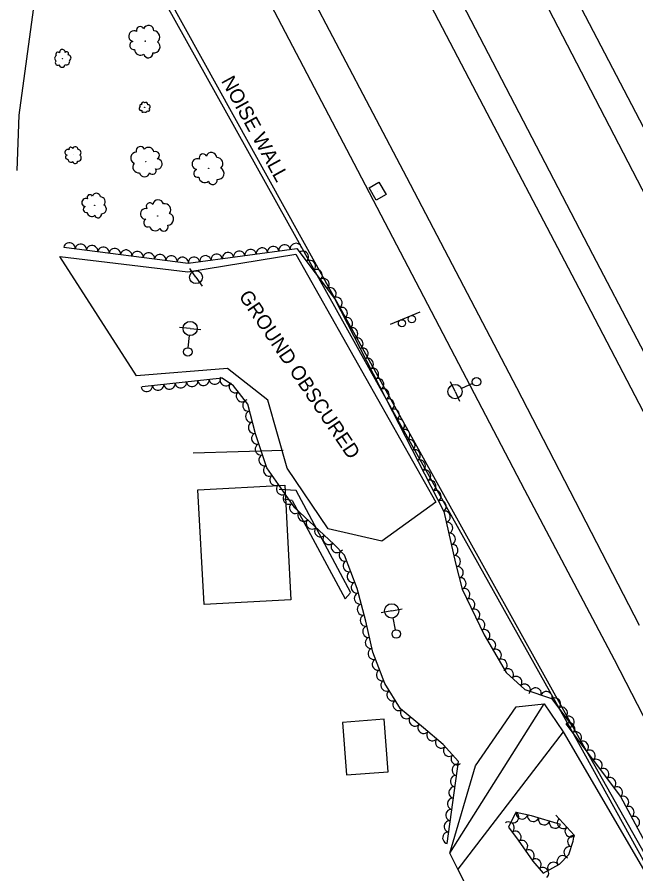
# Model space of a CAD drawing. Extents: x 1722896 to 1754269, y 648279 to 666297.
# Drawn here: x 1727428.2 to 1727645, y 654279.2 to 654579.3 of the extents above; entities that cross this region are included whole.
import ezdxf

# ---------------------------------------------------------------- set-up
doc = ezdxf.new("R2010")
doc.units = 0
for name, color, linetype in [('DESIGN - CENTERLINE - Proposed Text', 7, 'Continuous'), ('DESIGN - PUBLIC HEARING - Shapes', 7, 'Continuous'), ('DESIGN - SCRATCH - User 1', 7, 'Continuous'), ('SURVEY - CENTERLINE - Preliminary', 7, 'Continuous'), ('SURVEY - CENTERLINE - Preliminary Text', 7, 'Continuous'), ('SURVEY - DRAINAGE - Natural Features', 7, 'Continuous'), ('SURVEY - DTM - Breaklines', 7, 'Continuous'), ('SURVEY - VEGETATION - Features with Text', 7, 'Continuous')]:
    doc.layers.add(name, color=color, linetype=linetype)

msp = doc.modelspace()

# ---------------------------------------------------------------- linework, layer by layer
at = {"layer": 'DESIGN - CENTERLINE - Proposed Text'}
for points in [[(1727521.94, 654415.39), (1727524.08, 654375.16), (1727493.7, 654373.54), (1727491.56, 654413.77)], [(1727558.24, 654315), (1727556.82, 654333.41), (1727542.2, 654332.28), (1727543.62, 654313.88)]]:
    msp.add_lwpolyline(points, close=True, dxfattribs=at)
for points in [[(1727526, 654413.45), (1727519.97, 654413.84)], [(1727545.15, 654377.67), (1727526, 654413.45)], [(1727524.53, 654409.96), (1727521.55, 654410.51)], [(1727524.53, 654409.96), (1727543.11, 654375.61), (1727544.9, 654377.49)]]:
    msp.add_lwpolyline(points, dxfattribs=at)
at = {"layer": 'DESIGN - PUBLIC HEARING - Shapes'}
msp.add_line((1727559.02, 654471.72), (1727569.36, 654476.04), dxfattribs=at)
for centre in [(1727563.02, 654472.07), (1727566.48, 654473.51)]:
    msp.add_circle(centre, 1.25, dxfattribs=at)
at = {"layer": 'DESIGN - SCRATCH - User 1'}
for points in [[(1727621.97, 654330.39), (1727565.01, 654432.18), (1727473.36, 654596.48), (1727444.29, 654648.43), (1727445.92, 654649.54), (1727574.11, 654418.37), (1727622.54, 654331.36), (1727621.97, 654330.39)], [(1727622.54, 654331.36), (1727686.73, 654217.77), (1727717.7, 654165.84), (1727754.59, 654120.21), (1727781.55, 654068.35), (1727801.08, 654028.51), (1727824.69, 653960.51), (1727834.36, 653937.28), (1727857, 653885.22), (1727876.48, 653842.06), (1727927.37, 653734.57), (1727927.59, 653734.45)], [(1727927.59, 653734.45), (1727926.17, 653733.65), (1727871.54, 653849.39), (1727850.91, 653896.35), (1727825.81, 653953.49), (1727800.77, 654025.96), (1727785.37, 654057.35), (1727753.48, 654119.66), (1727717.18, 654164.37), (1727672.06, 654239.76), (1727621.97, 654330.39)]]:
    msp.add_lwpolyline(points, dxfattribs=at)
at = {"layer": 'SURVEY - CENTERLINE - Preliminary'}
for points in [[(1727443.16, 654495.41), (1727488, 654490.06), (1727525.83, 654496.28), (1727574.91, 654409.36), (1727555.92, 654395.79), (1727537.15, 654400.12), (1727522.77, 654421.34), (1727516.06, 654445.1), (1727501.95, 654456.21), (1727470.05, 654453.63), (1727443.16, 654495.41)], [(1727579.83, 654286.49), (1727588.84, 654317.11), (1727602.99, 654337.68), (1727612.89, 654338.81), (1727619.49, 654329.03), (1727582.65, 654280.92), (1727579.83, 654286.49)], [(1727612.89, 654338.81), (1727619.49, 654329.03), (1727662.34, 654255.54), (1727674.34, 654234.16), (1727664.05, 654232.84), (1727648.66, 654245.66), (1727604.39, 654235.79), (1727598.61, 654249.64), (1727582.65, 654280.92), (1727579.83, 654286.49), (1727612.89, 654338.81)]]:
    msp.add_lwpolyline(points, dxfattribs=at)
at = {"layer": 'SURVEY - CENTERLINE - Preliminary Text'}
for points in [[(1727480.36, 654860.59), (1727517.38, 654790.02), (1727553.54, 654721.23), (1727589.42, 654652.68), (1727621.82, 654590.18), (1727658.34, 654520.12), (1727699.55, 654441.02)], [(1727477.66, 654844.03), (1727487.15, 654825.93), (1727548.9, 654707.43), (1727604.51, 654601.23), (1727660.16, 654493.92), (1727693.17, 654431.8)], [(1727676.45, 654407.23), (1727629.94, 654496.13), (1727562.95, 654624.9), (1727499.94, 654745.76), (1727460.45, 654821.38)], [(1727670.06, 654398.14), (1727625.13, 654484.21), (1727587.89, 654555.22), (1727538.84, 654649.08), (1727490.42, 654741.64), (1727470.74, 654779.75)], [(1727462.93, 654717.36), (1727491.7, 654662.04), (1727529.25, 654590.6), (1727564.63, 654523.18), (1727603.1, 654449.52), (1727646.13, 654366.33)], [(1727459.16, 654693.93), (1727498.07, 654619.99), (1727547.4, 654525.69), (1727605.96, 654413.77), (1727637.32, 654354.34)], [(1727428.2, 654525.58), (1727428.87, 654544.95), (1727434.27, 654584.37), (1727440.35, 654629.65)], [(1727489.9, 654426.69), (1727521.41, 654427.67)], [(1727637.32, 654354.34), (1727659.52, 654311.28), (1727683.82, 654265.75), (1727710.26, 654216.86)]]:
    msp.add_lwpolyline(points, dxfattribs=at)
at = {"layer": 'SURVEY - DRAINAGE - Natural Features'}
msp.add_line((1727554.49, 654518.31), (1727554.49, 654518.31), dxfattribs=at)
msp.add_lwpolyline([(1727551.5, 654519.46), (1727554.96, 654521.48), (1727557.48, 654517.17), (1727554.03, 654515.14), (1727551.5, 654519.46)], dxfattribs=at)
at = {"layer": 'SURVEY - DTM - Breaklines'}
for p, q in [((1727490.86, 654488.21), (1727488.73, 654491.29)), ((1727490.86, 654488.21), (1727492.99, 654485.12)), ((1727488.82, 654470.23), (1727485.09, 654470.6)), ((1727488.82, 654470.23), (1727492.55, 654469.86)), ((1727488.15, 654463.51), (1727488.57, 654467.74)), ((1727581.63, 654448.15), (1727580.06, 654451.55)), ((1727587.76, 654450.97), (1727583.9, 654449.19)), ((1727581.63, 654448.15), (1727583.2, 654444.74)), ((1727559.42, 654371.34), (1727555.74, 654370.6)), ((1727559.42, 654371.34), (1727563.09, 654372.08)), ((1727560.74, 654364.72), (1727559.91, 654368.89))]:
    msp.add_line(p, q, dxfattribs=at)
for centre, radius in [((1727490.86, 654488.21), 2.25), ((1727488.82, 654470.23), 2.5), ((1727488, 654462.02), 1.5), ((1727589.12, 654451.6), 1.5), ((1727581.63, 654448.15), 2.5), ((1727559.42, 654371.34), 2.5), ((1727561.04, 654363.25), 1.5)]:
    msp.add_circle(centre, radius, dxfattribs=at)
at = {"layer": 'SURVEY - VEGETATION - Features with Text'}
for points in [[(1727444.56, 654498.67), (1727488.14, 654493.07), (1727526.25, 654498.26), (1727539.39, 654480.79), (1727577.64, 654406.11), (1727581.78, 654388.07), (1727584.1, 654378.91), (1727591.86, 654362.96), (1727599.52, 654349.78), (1727606.08, 654343.75), (1727615.4, 654340.62), (1727623.56, 654329.77)], [(1727578.88, 654289.91), (1727582.85, 654318.64), (1727577.44, 654324.54), (1727570.52, 654330.37), (1727562.55, 654337.09), (1727557.08, 654345.94), (1727552.82, 654356.93), (1727550.32, 654367.79), (1727547.3, 654379.17), (1727542.85, 654390.83), (1727539.15, 654394.72), (1727525.48, 654407.44), (1727515.71, 654421.44), (1727511.66, 654433.3), (1727508.99, 654443.79), (1727504.04, 654450.16), (1727500.03, 654452.86), (1727472.01, 654449.86)], [(1727620.44, 654331.82), (1727639.55, 654306.32), (1727668, 654253.51), (1727701.3, 654204.59), (1727718.06, 654176.14), (1727729.46, 654166.58), (1727734.69, 654156.89), (1727740.47, 654144.96), (1727749.36, 654127.63), (1727758.01, 654116.35), (1727776.45, 654083.72), (1727777.95, 654074.34), (1727772.29, 654075.58), (1727763.54, 654080.4), (1727757.81, 654069.22), (1727754.36, 654069.14), (1727749.06, 654073.59), (1727741.42, 654080.65), (1727731.8, 654075.75), (1727704.78, 654053.2)], [(1727618.54, 654296.53), (1727608.43, 654299.62), (1727603.08, 654300.72), (1727602.57, 654300.11), (1727600.37, 654295.57), (1727603.69, 654291.1), (1727608.9, 654283.69), (1727612.52, 654279.52), (1727618.26, 654282.64), (1727621.43, 654286.04), (1727622.96, 654290.65), (1727623.3, 654292.74), (1727616.9, 654299.76)]]:
    msp.add_lwpolyline(points, dxfattribs=at)
for centre, radius in [((1727473.07, 654570.87), 0.0661), ((1727444.13, 654564.75), 0.0346), ((1727472.89, 654547.69), 0.022), ((1727447.96, 654531.04), 0.0346), ((1727473.26, 654528.71), 0.0629), ((1727495.35, 654526.36), 0.0658), ((1727455.35, 654513.34), 0.0503), ((1727477.43, 654509.68), 0.0656)]:
    msp.add_circle(centre, radius, dxfattribs=at)
for centre, radius, start, end in [((1727469.19, 654572.6), 1.89, 62.0023, 255.422), ((1727471.29, 654574.73), 1.3, 21.9816, 200.7272), ((1727474.24, 654574.47), 1.89, 359.8654, 156.6543), ((1727476, 654572.31), 2.16, 308.9182, 86.4424), ((1727469.08, 654569.38), 1.44, 104.6209, 281.9401), ((1727476.14, 654568.86), 2.14, 259.814, 55.6525), ((1727442.39, 654564.86), 1.07, 116.2169, 243.0626), ((1727442.51, 654566.28), 0.753, 40.9299, 218.249), ((1727444.05, 654566.98), 0.99, 358.3112, 191.7309), ((1727445.53, 654566.48), 0.681, 318.2905, 137.0361), ((1727446.09, 654565.04), 0.992, 296.1743, 92.9633), ((1727471.41, 654567.97), 2.04, 179.908, 306.7537), ((1727474.19, 654566.61), 1.58, 190.0669, 5.0672), ((1727442.4, 654563.24), 0.828, 126.3758, 301.3761), ((1727443.91, 654562.84), 1.12, 196.1229, 351.9614), ((1727445.49, 654563.71), 1.13, 245.2271, 22.7513), ((1727471.55, 654547.23), 0.629, 104.9373, 298.357), ((1727471.58, 654548.23), 0.433, 64.9166, 243.6623), ((1727472.36, 654548.83), 0.631, 42.8005, 199.5894), ((1727473.28, 654548.71), 0.719, 351.8532, 129.3774), ((1727474.13, 654546.91), 0.527, 233.0019, 48.0022), ((1727474.1, 654547.9), 0.714, 302.749, 98.5875), ((1727472.26, 654546.42), 0.479, 147.556, 324.8751), ((1727473.15, 654546.61), 0.679, 222.843, 349.6887), ((1727445.93, 654531.95), 0.989, 61.9058, 255.3255), ((1727447.03, 654533.06), 0.68, 21.8851, 200.6308), ((1727448.57, 654532.92), 0.991, 359.769, 156.5579), ((1727449.49, 654531.8), 1.13, 308.8217, 86.3459), ((1727471.4, 654532.46), 1.51, 21.6537, 196.654), ((1727474.25, 654531.73), 1.94, 11.4948, 138.3405), ((1727476.7, 654530.86), 1.37, 296.2078, 113.5269), ((1727445.86, 654530.27), 0.753, 104.5245, 281.8436), ((1727447.09, 654529.53), 1.07, 179.8115, 306.6572), ((1727449.56, 654529.99), 1.12, 259.7175, 55.556), ((1727470.01, 654529.99), 2.04, 91.4008, 247.2393), ((1727477.21, 654527.84), 1.8, 253.5891, 87.0088), ((1727491.37, 654527.82), 1.88, 66.0002, 259.4199), ((1727493.31, 654530.08), 1.3, 25.9795, 204.7251), ((1727496.26, 654530.02), 1.89, 3.8633, 160.6523), ((1727498.15, 654528), 2.15, 312.9161, 90.4403), ((1727448.54, 654528.81), 0.827, 189.9704, 4.9707), ((1727470.8, 654526.8), 2.05, 140.505, 278.0292), ((1727498.54, 654524.59), 2.14, 263.8119, 59.6504), ((1727472.86, 654525.13), 1.8, 191.4523, 348.2412), ((1727475.65, 654525.45), 1.24, 213.5684, 32.3141), ((1727491.48, 654524.61), 1.43, 108.6188, 285.938), ((1727493.9, 654523.37), 2.03, 183.9059, 310.7516), ((1727496.75, 654522.21), 1.58, 194.0648, 9.0651), ((1727455.95, 654516.15), 1.44, 5.8636, 162.6525), ((1727452.28, 654514.34), 1.44, 68.0004, 261.4201), ((1727453.7, 654516.12), 0.989, 27.9797, 206.7254), ((1727457.45, 654514.66), 1.64, 314.9163, 92.4405), ((1727477.63, 654513.43), 1.88, 14.6718, 171.4607), ((1727452.45, 654511.9), 1.09, 110.6191, 287.9382), ((1727457.83, 654512.07), 1.63, 265.8121, 61.6506), ((1727473.27, 654510.36), 1.87, 76.8086, 270.2283), ((1727474.74, 654512.94), 1.29, 36.7879, 215.5336), ((1727479.87, 654511.81), 2.14, 323.7245, 101.2487), ((1727454.33, 654511.01), 1.55, 185.9061, 312.7518), ((1727456.53, 654510.21), 1.2, 196.065, 11.0653), ((1727473.97, 654507.24), 1.43, 119.4273, 296.7464), ((1727480.88, 654508.54), 2.13, 274.6203, 70.4588), ((1727476.57, 654506.48), 2.02, 194.7143, 321.56), ((1727479.58, 654505.89), 1.57, 204.8732, 19.8735)]:
    msp.add_arc(centre, radius, start, end, dxfattribs=at)
for centre, major_axis in [((1727446.55, 654498.42), (1.98, -0.26)), ((1727450.52, 654497.91), (1.98, -0.26)), ((1727454.48, 654497.4), (1.98, -0.26)), ((1727521.89, 654497.66), (1.98, 0.27)), ((1727525.86, 654498.2), (1.98, 0.27)), ((1727458.45, 654496.89), (1.98, -0.26)), ((1727462.42, 654496.38), (1.98, -0.26)), ((1727466.39, 654495.87), (1.98, -0.26)), ((1727470.35, 654495.35), (1.98, -0.26)), ((1727474.32, 654494.84), (1.98, -0.26)), ((1727478.29, 654494.33), (1.98, -0.26)), ((1727498.11, 654494.42), (1.98, 0.27)), ((1727502.08, 654494.96), (1.98, 0.27)), ((1727506.04, 654495.5), (1.98, 0.27)), ((1727510, 654496.04), (1.98, 0.27)), ((1727513.97, 654496.58), (1.98, 0.27)), ((1727517.93, 654497.12), (1.98, 0.27)), ((1727528.42, 654495.38), (1.2, -1.6)), ((1727482.25, 654493.82), (1.98, -0.26)), ((1727486.22, 654493.31), (1.98, -0.26)), ((1727490.19, 654493.34), (1.98, 0.27)), ((1727494.15, 654493.88), (1.98, 0.27)), ((1727530.82, 654492.18), (1.2, -1.6)), ((1727533.22, 654488.98), (1.2, -1.6)), ((1727535.63, 654485.79), (1.2, -1.6)), ((1727538.03, 654482.59), (1.2, -1.6)), ((1727540.18, 654479.24), (0.91, -1.78)), ((1727542.01, 654475.68), (0.91, -1.78)), ((1727543.83, 654472.12), (0.91, -1.78)), ((1727545.65, 654468.55), (0.91, -1.78)), ((1727547.48, 654464.99), (0.91, -1.78)), ((1727549.3, 654461.43), (0.91, -1.78)), ((1727551.12, 654457.87), (0.91, -1.78)), ((1727552.95, 654454.31), (0.91, -1.78)), ((1727485.56, 654451.31), (-1.99, -0.21)), ((1727489.53, 654451.74), (-1.99, -0.21)), ((1727493.51, 654452.16), (-1.99, -0.21)), ((1727497.49, 654452.59), (-1.99, -0.21)), ((1727501.23, 654452.06), (-1.66, 1.12)), ((1727504.42, 654449.68), (-1.23, 1.58)), ((1727554.77, 654450.75), (0.91, -1.78)), ((1727473.62, 654450.04), (-1.99, -0.21)), ((1727477.6, 654450.46), (-1.99, -0.21)), ((1727481.58, 654450.89), (-1.99, -0.21)), ((1727556.59, 654447.19), (0.91, -1.78)), ((1727506.87, 654446.52), (-1.23, 1.58)), ((1727558.42, 654443.63), (0.91, -1.78)), ((1727509.13, 654443.27), (-0.49, 1.94)), ((1727560.24, 654440.07), (0.91, -1.78)), ((1727510.11, 654439.39), (-0.49, 1.94)), ((1727511.1, 654435.51), (-0.49, 1.94)), ((1727562.06, 654436.51), (0.91, -1.78)), ((1727512.22, 654431.68), (-0.65, 1.89)), ((1727563.89, 654432.95), (0.91, -1.78)), ((1727565.71, 654429.39), (0.91, -1.78)), ((1727513.51, 654427.89), (-0.65, 1.89)), ((1727567.54, 654425.83), (0.91, -1.78)), ((1727514.8, 654424.11), (-0.65, 1.89)), ((1727569.36, 654422.27), (0.91, -1.78)), ((1727516.39, 654420.47), (-1.14, 1.64)), ((1727518.68, 654417.19), (-1.14, 1.64)), ((1727571.18, 654418.71), (0.91, -1.78)), ((1727520.97, 654413.91), (-1.14, 1.64)), ((1727573.01, 654415.15), (0.91, -1.78)), ((1727523.26, 654410.63), (-1.14, 1.64)), ((1727574.83, 654411.59), (0.91, -1.78)), ((1727576.65, 654408.03), (0.91, -1.78)), ((1727525.56, 654407.37), (-1.46, 1.36)), ((1727578.05, 654404.32), (0.45, -1.95)), ((1727528.49, 654404.64), (-1.46, 1.36)), ((1727531.42, 654401.92), (-1.46, 1.36)), ((1727534.35, 654399.19), (-1.46, 1.36)), ((1727578.94, 654400.42), (0.45, -1.95)), ((1727537.28, 654396.47), (-1.46, 1.36)), ((1727579.84, 654396.52), (0.45, -1.95)), ((1727540.14, 654393.68), (-1.38, 1.45)), ((1727580.74, 654392.62), (0.45, -1.95)), ((1727542.87, 654390.76), (-0.71, 1.87)), ((1727544.3, 654387.03), (-0.71, 1.87)), ((1727581.63, 654388.72), (0.45, -1.95)), ((1727582.6, 654384.84), (0.49, -1.94)), ((1727545.73, 654383.29), (-0.71, 1.87)), ((1727583.58, 654380.96), (0.49, -1.94)), ((1727547.15, 654379.55), (-0.71, 1.87)), ((1727584.92, 654377.22), (0.88, -1.8)), ((1727548.22, 654375.7), (-0.51, 1.93)), ((1727549.25, 654371.83), (-0.51, 1.93)), ((1727586.67, 654373.62), (0.88, -1.8)), ((1727588.42, 654370.02), (0.88, -1.8)), ((1727550.27, 654367.97), (-0.51, 1.93)), ((1727590.17, 654366.43), (0.88, -1.8)), ((1727551.18, 654364.07), (-0.45, 1.95)), ((1727591.93, 654362.83), (1.01, -1.73)), ((1727552.07, 654360.17), (-0.45, 1.95)), ((1727593.94, 654359.38), (1.01, -1.73)), ((1727553.06, 654356.3), (-0.72, 1.86)), ((1727595.95, 654355.92), (1.01, -1.73)), ((1727554.51, 654352.57), (-0.72, 1.86)), ((1727597.96, 654352.46), (1.01, -1.73)), ((1727555.96, 654348.84), (-0.72, 1.86)), ((1727600.19, 654349.17), (1.47, -1.35)), ((1727557.55, 654345.19), (-1.05, 1.7)), ((1727603.13, 654346.46), (1.47, -1.35)), ((1727559.65, 654341.78), (-1.05, 1.7)), ((1727606.07, 654343.76), (1.47, -1.35)), ((1727609.86, 654342.48), (1.9, -0.64)), ((1727613.65, 654341.21), (1.9, -0.64)), ((1727616.7, 654338.89), (1.2, -1.6)), ((1727561.75, 654338.38), (-1.05, 1.7)), ((1727619.1, 654335.7), (1.2, -1.6)), ((1727564.45, 654335.49), (-1.53, 1.29)), ((1727621.5, 654332.5), (1.2, -1.6)), ((1727567.51, 654332.91), (-1.53, 1.29)), ((1727570.56, 654330.33), (-1.53, 1.29)), ((1727621.63, 654330.21), (1.2, -1.6)), ((1727573.62, 654327.76), (-1.53, 1.29)), ((1727624.03, 654327.01), (1.2, -1.6)), ((1727576.68, 654325.18), (-1.53, 1.29)), ((1727626.43, 654323.81), (1.2, -1.6)), ((1727579.47, 654322.32), (-1.35, 1.47)), ((1727628.83, 654320.61), (1.2, -1.6)), ((1727582.18, 654319.37), (-1.35, 1.47)), ((1727631.23, 654317.41), (1.2, -1.6)), ((1727582.44, 654315.66), (0.27, 1.98)), ((1727633.63, 654314.21), (1.2, -1.6)), ((1727581.89, 654311.7), (0.27, 1.98)), ((1727636.03, 654311.01), (1.2, -1.6)), ((1727581.34, 654307.74), (0.27, 1.98)), ((1727638.43, 654307.81), (1.2, -1.6)), ((1727580.8, 654303.78), (0.27, 1.98)), ((1727640.56, 654304.44), (0.95, -1.76)), ((1727580.25, 654299.81), (0.27, 1.98)), ((1727642.46, 654300.92), (0.95, -1.76)), ((1727602.06, 654299.06), (-0.87, -1.8)), ((1727605.07, 654300.31), (-1.96, 0.4)), ((1727608.98, 654299.45), (-1.91, 0.58)), ((1727612.81, 654298.28), (-1.91, 0.58)), ((1727619.38, 654297.04), (-1.35, 1.48)), ((1727644.36, 654297.4), (0.95, -1.76)), ((1727579.7, 654295.85), (0.27, 1.98)), ((1727600.45, 654295.47), (1.19, -1.61)), ((1727616.63, 654297.11), (-1.91, 0.58)), ((1727622.08, 654294.08), (-1.35, 1.48)), ((1727579.15, 654291.89), (0.27, 1.98)), ((1727602.83, 654292.26), (1.19, -1.61)), ((1727622.94, 654290.59), (0.63, 1.9)), ((1727605.16, 654289.01), (1.15, -1.64)), ((1727607.46, 654285.73), (1.15, -1.64)), ((1727621.68, 654286.79), (0.63, 1.9)), ((1727609.88, 654282.55), (1.31, -1.51)), ((1727616.02, 654281.41), (1.76, 0.95)), ((1727619.25, 654283.69), (1.36, 1.46)), ((1727612.51, 654279.53), (1.31, -1.51))]:
    msp.add_ellipse(centre, major_axis=major_axis, ratio=0.940188, start_param=0, end_param=3.141593, dxfattribs=at)

# ---------------------------------------------------------------- texts
at = {"layer": 'DESIGN - SCRATCH - User 1'}
msp.add_text('NOISE WALL', height=5, rotation=298.6712, dxfattribs=at).set_placement((1727499.58, 654556.97))
at = {"layer": 'SURVEY - CENTERLINE - Preliminary'}
msp.add_text('GROUND OBSCURED', height=5, rotation=304.1049, dxfattribs=at).set_placement((1727505.66, 654481.55))

doc.saveas('drawing.dxf')
